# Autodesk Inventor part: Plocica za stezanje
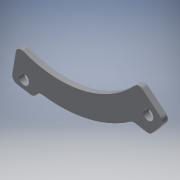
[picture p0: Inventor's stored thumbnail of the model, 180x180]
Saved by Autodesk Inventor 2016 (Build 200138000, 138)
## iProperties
Created: 2015-08
Part Number: Plocica za stezanje
Material: Generic
Document SubType Name: Modeling
Designer: Ugljesa
Density: 1 g/cm^3
Appearance: Default
Author: Ugljesa
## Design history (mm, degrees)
sketch "Sketch1"
  geometry: L1 (-99.591, -26.253)-(-100.857, -27.789); L2 (-105.54, -29.54)-(-117.488, -27.54); L3 (-121.594, -21.784)-(-118.516, -3.391); L4 (-6.118, 24.046)-(9.416, 11.241); L5 (10.093, 4.202)-(2.389, -5.145); L6 (-2.295, -6.896)-(-12.882, -5.124); L7 (-79.322, 84.389)-(-22.296, 37.381); C1 r 4.5 at (-1.155, 6.995) reference; C2 r 4.5 at (-111.3, -20.86); C3 r 4.5 at (-111.3, -20.86) reference; A1 r 90 centre (-79.322, 84.389) between (-111.781, 0.447) and (-12.984, 23.567); A2 r 110 centre (-79.322, 84.389) between (-95.02, -24.485) and (-16.56, -5.949); A3 r 5 centre (-1.47, -1.964) between (-2.295, -6.896) and (2.389, -5.145); A4 r 5 centre (-13.708, -10.055) between (-12.882, -5.124) and (-16.56, -5.949); A5 r 5 centre (-95.733, -29.433) between (-95.02, -24.485) and (-99.591, -26.253); A6 r 5 centre (-104.715, -24.608) between (-105.54, -29.54) and (-100.857, -27.789); A7 r 5 centre (-116.662, -22.609) between (-121.594, -21.784) and (-117.488, -27.54); A8 r 5 centre (-113.585, -4.217) between (-111.781, 0.447) and (-118.516, -3.391); A9 r 5 centre (-9.299, 20.188) between (-6.118, 24.046) and (-12.984, 23.567); A10 r 5 centre (6.235, 7.383) between (10.093, 4.202) and (9.416, 11.241); 9 further points
  constraints: 26 point on circle, 16 tangent, 14 end point, 12 centre point, 12 point on line, 7 equal radius, 2 coincident, 2 perpendicular, 1 collinear, 2 other
  dimensions: "d1" = 110 radius of A2; "d2" = 90 radius of A1; "d4" = 60 deg angle of L4 L3; "d5" = 30 distance of point (-122.419, -26.715) point (-117.468, 2.873); "d8" = 30 distance of point (-9.875, 27.143) point (13.274, 8.061); "d9" = 10 distance from line of L4 C1.centre; "d10" = 10 distance from line of L3 C2.centre; "d11" = 20 distance of point (-102.693, -30.016) point (-122.419, -26.715); "d12" = 20 distance of point (13.274, 8.061) point (0.552, -7.372); "d13" = 30 deg angle of L3 L1; "d14" = 30 deg angle of L7 L6; "d15" = 5 radius of A3
extrude "Extrusion1" new body sketch "Sketch1" distance "d16" = 3; taper "d17" = 0 deg
body "Solid1"
node "Reference1"
